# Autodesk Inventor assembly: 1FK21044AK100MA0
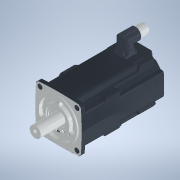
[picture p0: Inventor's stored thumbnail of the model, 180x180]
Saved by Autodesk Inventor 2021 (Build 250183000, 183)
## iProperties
Category: PARTsolutions
Created: 2026-06
Part Number: 1FK21044AK100MA0
Catalog Web Link: www.3dfindit.com
Description: 1FK21044AK100MA0-Servo synchronous motor
Document SubType Name: Assembly
Designer: psAdmin
Mass: 801.95 g
Surface Area: 1112.42 cm^2
Volume: 801.95 cm^3
Density: 1 g/cm^3
Title: 1FK21044AK100MA0
Author: Cadenas PARTsolutions
Comments: Servo synchronous motor
PSOL_IDENT_0: {$CADENAS_DATA/23d-libs/siemens_ag/_cat_/5e/d8/1fk21044ak100ma0.prj},193 {STYP=ASS},{VTYP=3D},{NB=1F
PSOL_IDENT_1: K21044AK100MA0},{LINA=1FK21044AK100MA0},{NN=1FK21044AK100MA0},{DATE=19.08.2025 14:00:41},{GEOMDATE=3
PSOL_IDENT_2: 0.07.2025 02:00:53},{VERSION=},{LINEID=10},{WBVAR=},{WBNUMERIC=}  {NB=1FK21044AK100MA0},{LINA=1FK210
PSOL_IDENT_3: 44AK100MA0},{KT=DUMMY},{PREVIEW=../../../_pool_/cb/72/p_d211_xx_00434j.png},{DESCSHORT=SIMOTICS S-1F
PSOL_IDENT_4: K2 HD, SINAMICS S210 3AC 400V-480V, 0.95 Nm, 6000 rpm},{DESCLONG=SIMOTICS S-1FK2 HD servo motor M0=1
PSOL_IDENT_5: .27 Nm; PN = 0.6 kW at nN=6000 rpm (380-480 V); PN = 0.4 kW at nN=3000 rpm (200-240 V); with holding
PSOL_IDENT_6: brake; degree of protection IP64; cylindrical shaft D19x40mm; absolute encoder 22-bit + 12-bit mult
PSOL_IDENT_7: iturn (encoder AM22DQC); with OCC interface; plug size M17, rotatable; SIMOTICS S-1FK2 servomotorfor
PSOL_IDENT_8: a wide range of uses in industrial environments. SIMOTICS S‑1FK2 servomotors are compact synchronou
PSOL_IDENT_9: s motors with a high dynamic performance that set themselves apart as a result of their high power d
PSOL_IDENT_10: ensity, degree of protection and overload capability. The motors are available in two variants: as H
PSOL_IDENT_11: igh Dynamic variant (highest dynamic performance as a result of the low intrinsic moment of inertia
PSOL_IDENT_12: for applications demanding a high dynamic performance with low moved masses) - and as Compact varian
PSOL_IDENT_13: t (precise and stable closed-loop control for medium up to large moved masses as a result of a mediu
PSOL_IDENT_14: m intrinsic moment of inertia). SIMOTICSS‑1FK2 servomotors fully exploit their strengths in a system
PSOL_IDENT_15: with the SINAMICSS210 frequency converter and simple connection using the one cable connection (OCC
PSOL_IDENT_16: ). Advantages include the short control and positioning times, fast and precise correction of distur
PSOL_IDENT_17: bing quantities as well as stable control with a high dynamic performance. The servo motors can be c
PSOL_IDENT_18: onfigured to address a wide range of requirements. For example with and without holding brake, IP64
PSOL_IDENT_19: or IP65 degree of protection, singleturn or multiturn absolute encoders - to name just a few. Furthe
PSOL_IDENT_20: r, the servomotors are available in different shaft heights extending from 20 to 100. A shaft sealin
PSOL_IDENT_21: g ring is available to achieve an IP65 degree of protection and for subsequent mounting at the motor
PSOL_IDENT_22: or as spare part. SIMOTICS - the optimum motor for each and every motion control application.},{INT
PSOL_IDENT_23: NO=804766910005},{SUPPLIERALTNO=1FK2104-4AK10-0MA0},{MANUID=1FK21044AK100MA0},{MANUNAME=Siemens},{MA
PSOL_IDENT_24: NUTYPEDESC=Synchronous motor 1FK2-HD 1,27 Nm},{AAU732=SIMOTICS},{AAO057=S-1FK2},{AAU734=SIMOTICS S-1
PSOL_IDENT_25: FK2 HD servo motor M0=1.27 Nm; PN = 0.6 kW at nN=6000 rpm (380-480 V); PN = 0.4 kW at nN=3000 rpm (2
PSOL_IDENT_26: 00-240 V); with holding brake; degree of protection IP64; cylindrical shaft D19x40mm; absolute encod
PSOL_IDENT_27: er 22-bit + 12-bit multiturn (encoder AM22DQC); with OCC interface; plug size M17, rotatable;},{AAW3
PSOL_IDENT_28: 38=Synchronous motor 1FK2-HD 1,27 Nm},{AAO742=SIMOTICS},{AAO663=4042948691076},{NOCUPEROU=1},{PRICEQ
PSOL_IDENT_29: UANTITY=1},{QUANTITYMIN=1},{QUANTITYINT=1},{CTN=85015100},{COO=DE},{AAO676=1FK2104-4AK10-0MA0},{AAO6
PSOL_IDENT_30: 77=Siemens AG},{ORDERUNIT=C62},{CONTENTUNIT=C62}
NB: 1FK21044AK100MA0
NN: 1FK21044AK100MA0
NT: Servo synchronous motor
NBSYN: $MANUID.
LINA: 1FK21044AK100MA0
CATALOG: SIEMENS
PREVIEW: ../../../_pool_/cb/72/p_d211_xx_00434j.png
DESCSHORT: SIMOTICS S-1FK2 HD, SINAMICS S210 3AC 400V-480V, 0.95 Nm, 6000 rpm
DESCLONG: SIMOTICS S-1FK2 HD servo motor M0=1.27 Nm; PN = 0.6 kW at nN=6000 rpm (380-480 V); PN = 0.4 kW at nN=3000 rpm (200-240 V); with holding brake; degree of protect
INTNO: 804766910005
SUPPLIERALTNO: 1FK2104-4AK10-0MA0
MANUID: 1FK21044AK100MA0
MANUNAME: Siemens
MANUTYPEDESC: Synchronous motor 1FK2-HD 1,27 Nm
AAU732: SIMOTICS
AAO057: S-1FK2
AAU734: SIMOTICS S-1FK2 HD servo motor M0=1.27 Nm; PN = 0.6 kW at nN=6000 rpm (380-480 V); PN = 0.4 kW at nN=3000 rpm (200-240 V); with holding brake; degree of protect
AAW338: Synchronous motor 1FK2-HD 1,27 Nm
AAO742: SIMOTICS
AAO663: 4042948691076.0
NOCUPEROU: 1
PRICEQUANTITY: 1
QUANTITYMIN: 1
QUANTITYINT: 1
CTN: 85015100
COO: DE
ARTICLENO: 1FK21044AK100MA0
BOMINFO: 1FK21044AK100MA0
CREATOR: CADENAS GmbH
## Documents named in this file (24)
- e:\temp\worker_COMMON_20\temp\tmp_1756_10_uMt37\format_0\1FK21044AK100MA0.iam
- e:\temp\worker_COMMON_20\temp\tmp_1756_10_uMt37\format_0\1FK21044AK100MA0_PART1.ipt
- e:\temp\worker_COMMON_20\temp\tmp_1756_10_uMt37\format_0\1FK21044AK100MA0_PART2.ipt
- e:\temp\worker_COMMON_20\temp\tmp_1756_10_uMt37\format_0\1FK21044AK100MA0_PART3.ipt
- e:\temp\worker_COMMON_20\temp\tmp_1756_10_uMt37\format_0\1FK21044AK100MA0_PART4.ipt
- e:\temp\worker_COMMON_20\temp\tmp_1756_10_uMt37\format_0\1FK21044AK100MA0_PART5.ipt
- e:\temp\worker_COMMON_20\temp\tmp_1756_10_uMt37\format_0\1FK21044AK100MA0_PART6.ipt
- e:\temp\worker_COMMON_20\temp\tmp_1756_10_uMt37\format_0\1FK21044AK100MA0_PART7.ipt
- e:\temp\worker_COMMON_20\temp\tmp_1756_10_uMt37\format_0\1FK21044AK100MA0_PART8.ipt
- e:\temp\worker_COMMON_20\temp\tmp_1756_10_uMt37\format_0\1FK21044AK100MA0_PART9.ipt
- e:\temp\worker_COMMON_20\temp\tmp_1756_10_uMt37\format_0\1FK21044AK100MA0_PART10.ipt
- e:\temp\worker_COMMON_20\temp\tmp_1756_10_uMt37\format_0\1FK21044AK100MA0_PART11.ipt
- e:\temp\worker_COMMON_20\temp\tmp_1756_10_uMt37\format_0\1FK21044AK100MA0_PART12.ipt
- e:\temp\worker_COMMON_20\temp\tmp_1756_10_uMt37\format_0\1FK21044AK100MA0_PART13.ipt
- e:\temp\worker_COMMON_20\temp\tmp_1756_10_uMt37\format_0\1FK21044AK100MA0_PART14.ipt
- e:\temp\worker_COMMON_20\temp\tmp_1756_10_uMt37\format_0\1FK21044AK100MA0_PART15.ipt
- e:\temp\worker_COMMON_20\temp\tmp_1756_10_uMt37\format_0\1FK21044AK100MA0_PART16.ipt
- e:\temp\worker_COMMON_20\temp\tmp_1756_10_uMt37\format_0\1FK21044AK100MA0_PART17.ipt
- e:\temp\worker_COMMON_20\temp\tmp_1756_10_uMt37\format_0\1FK21044AK100MA0_PART18.ipt
- e:\temp\worker_COMMON_20\temp\tmp_1756_10_uMt37\format_0\1FK21044AK100MA0_PART19.ipt
- e:\temp\worker_COMMON_20\temp\tmp_1756_10_uMt37\format_0\1FK21044AK100MA0_PART20.ipt
- e:\temp\worker_COMMON_20\temp\tmp_1756_10_uMt37\format_0\1FK21044AK100MA0_PART21.ipt
- e:\temp\worker_COMMON_20\temp\tmp_1756_10_uMt37\format_0\1FK21044AK100MA0_PART22.ipt
- e:\temp\worker_COMMON_20\temp\tmp_1756_10_uMt37\format_0\1FK21044AK100MA0_PART23.ipt
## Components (23 placed, 23 different names)
1. 1FK21044AK100MA0_PART1:1
2. 1FK21044AK100MA0_PART2:1
3. 1FK21044AK100MA0_PART3:1
4. 1FK21044AK100MA0_PART4:1
5. 1FK21044AK100MA0_PART5:1
6. 1FK21044AK100MA0_PART6:1
7. 1FK21044AK100MA0_PART7:1
8. 1FK21044AK100MA0_PART8:1
9. 1FK21044AK100MA0_PART9:1
10. 1FK21044AK100MA0_PART10:1
11. 1FK21044AK100MA0_PART11:1
12. 1FK21044AK100MA0_PART12:1
13. 1FK21044AK100MA0_PART13:1
14. 1FK21044AK100MA0_PART14:1
15. 1FK21044AK100MA0_PART15:1
16. 1FK21044AK100MA0_PART16:1
17. 1FK21044AK100MA0_PART17:1
18. 1FK21044AK100MA0_PART18:1
19. 1FK21044AK100MA0_PART19:1
20. 1FK21044AK100MA0_PART20:1
21. 1FK21044AK100MA0_PART21:1
22. 1FK21044AK100MA0_PART22:1
23. 1FK21044AK100MA0_PART23:1
